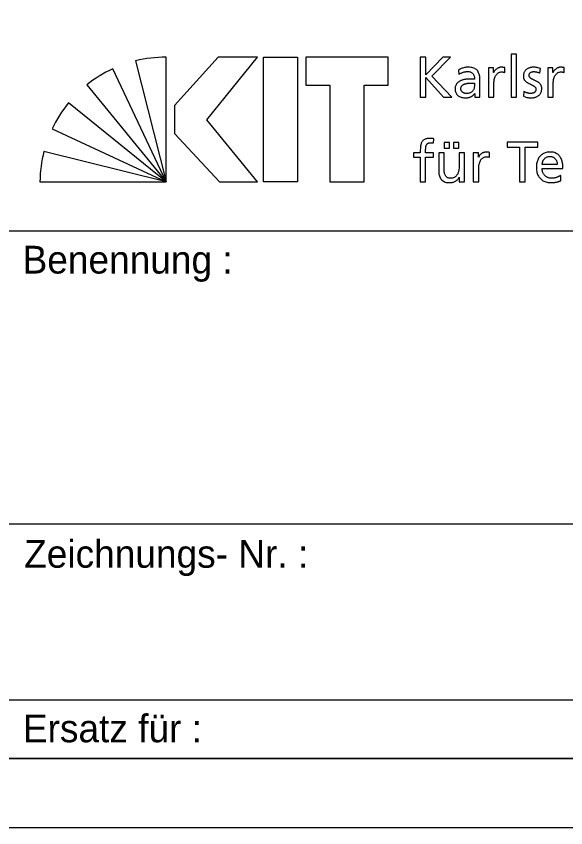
# Model space of a CAD drawing. Extents: x 0 to 75, y 0 to 42.1.
# Drawn here: x 70.583 to 72.566, y 0 to 2.927 of the extents above; entities that cross this region are included whole.
import ezdxf

# ---------------------------------------------------------------- set-up
doc = ezdxf.new("R2010")
doc.units = 0
doc.layers.add('90_Plankopf', color=7, linetype='Continuous')

msp = doc.modelspace()

# ---------------------------------------------------------------- linework, layer by layer
at = {"layer": '90_Plankopf'}
for p, q in [((71.0137, 2.7666), (71.124, 2.3293)), ((71.124, 2.3293), (71.124, 2.7792)), ((72.0405, 2.7793), (72.0405, 2.6353)), ((71.124, 2.3293), (70.9317, 2.7376)), ((72.179, 2.7331), (72.18, 2.7166)), ((72.3463, 2.7242), (72.3463, 2.7416)), ((72.4728, 2.722), (72.4745, 2.7389)), ((72.5606, 2.7242), (72.5606, 2.7416)), ((72.2559, 2.6559), (72.2559, 2.6995)), ((70.8372, 2.6793), (71.124, 2.3293)), ((72.2365, 2.6854), (72.2365, 2.6761)), ((72.0405, 2.6353), (72.0611, 2.6353)), ((72.1253, 2.6353), (72.1554, 2.6353)), ((72.4149, 2.6559), (72.4138, 2.6386)), ((71.124, 2.3293), (70.7717, 2.6143)), ((70.712, 2.5207), (71.124, 2.3293)), ((72.0887, 2.4696), (72.0895, 2.4853)), ((71.124, 2.3293), (70.6829, 2.4394)), ((72.2913, 2.4182), (72.2913, 2.4356)), ((72.5353, 2.392), (72.4808, 2.392)), ((72.4808, 2.3776), (72.5559, 2.3776)), ((72.5479, 2.3337), (72.5479, 2.353)), ((70.6682, 2.3293), (71.124, 2.3293)), ((70.55, 2.1535), (74.75, 2.1535)), ((70.55, 1.096), (74.75, 1.096)), ((70.55, 0.4615), (74.75, 0.4615)), ((74.75, 0.25), (65.856, 0.25)), ((66.44, 0.25), (74.75, 0.25)), ((66.44, 0.25), (74.75, 0.25))]:
    msp.add_line(p, q, dxfattribs=at)
for points in [[(0, 42.05), (75, 42.05), (75, 0), (0, 0)], [(71.4533, 2.7793), (71.3118, 2.7793), (71.1536, 2.6049), (71.1536, 2.5046), (71.3169, 2.3293), (71.4542, 2.3293), (71.2711, 2.5531)], [(71.5985, 2.7793), (71.5985, 2.3293), (71.4751, 2.3293), (71.4751, 2.7793)], [(71.6281, 2.7793), (71.6281, 2.678), (71.7151, 2.678), (71.7151, 2.3293), (71.8385, 2.3293), (71.8385, 2.678), (71.9255, 2.678), (71.9255, 2.7793)]]:
    msp.add_lwpolyline(points, close=True, dxfattribs=at)
for points in [[(59.6038, 0.25), (74.75, 0.25), (74.75, 41.8), (59.6038, 41.8)], [(72.369, 2.6353), (72.3884, 2.6353), (72.3884, 2.79), (72.369, 2.79), (72.369, 2.6353)], [(72.1554, 2.6353), (72.0824, 2.7112), (72.15, 2.7793), (72.1226, 2.7793), (72.0611, 2.716), (72.0611, 2.7793), (72.0405, 2.7793)], [(72.3061, 2.7242), (72.3057, 2.7242), (72.3057, 2.7405), (72.2875, 2.7405), (72.2875, 2.6353), (72.3069, 2.6353), (72.3069, 2.6832)], [(72.5203, 2.7242), (72.5199, 2.7242), (72.5199, 2.7405), (72.5018, 2.7405), (72.5018, 2.6353), (72.5212, 2.6353), (72.5212, 2.6832)], [(72.0611, 2.6353), (72.0611, 2.7059), (72.1253, 2.6353)], [(72.2382, 2.6489), (72.2386, 2.6489), (72.2386, 2.6353), (72.2567, 2.6353)], [(72.1277, 2.4713), (72.1277, 2.4506), (72.1471, 2.4506), (72.1471, 2.4713), (72.1277, 2.4713)], [(72.1615, 2.4713), (72.1615, 2.4506), (72.1809, 2.4506), (72.1809, 2.4713), (72.1615, 2.4713)], [(72.3995, 2.3293), (72.4201, 2.3293), (72.4201, 2.4552), (72.4649, 2.4552), (72.4649, 2.4733), (72.3547, 2.4733), (72.3547, 2.4552), (72.3995, 2.4552), (72.3995, 2.3293)], [(72.0412, 2.4443), (72.0412, 2.4346), (72.0165, 2.4346), (72.0165, 2.4189), (72.0412, 2.4189), (72.0412, 2.3293), (72.0606, 2.3293), (72.0606, 2.4189), (72.0885, 2.4189), (72.0885, 2.4346), (72.0606, 2.4346), (72.0606, 2.4459)], [(72.1271, 2.3801), (72.1271, 2.4346), (72.1077, 2.4346), (72.1077, 2.372)], [(72.2007, 2.3293), (72.2007, 2.4346), (72.1813, 2.4346), (72.1813, 2.3859)], [(72.2511, 2.4182), (72.2507, 2.4182), (72.2507, 2.4346), (72.2325, 2.4346), (72.2325, 2.3293), (72.2519, 2.3293), (72.2519, 2.3772)], [(72.1816, 2.346), (72.182, 2.346), (72.182, 2.3293), (72.2007, 2.3293)]]:
    msp.add_lwpolyline(points, dxfattribs=at)
for centre, start, end in [((71.1224, 2.3028), 89.8053, 103.1895), ((71.1331, 2.3059), 115.0126, 128.3968), ((71.1408, 2.3131), 140.7898, 154.174), ((71.1446, 2.3219), 165.7222, 179.1064)]:
    msp.add_arc(centre, 0.4764, start, end, dxfattribs=at)
for points in [[(72.2559, 2.6995), (72.256, 2.709), (72.2545, 2.717), (72.2517, 2.7235), (72.2488, 2.73), (72.2442, 2.7348), (72.238, 2.7381), (72.2317, 2.7413), (72.2236, 2.743), (72.2136, 2.743), (72.2069, 2.743), (72.2007, 2.742), (72.1949, 2.7402), (72.1891, 2.7384), (72.1838, 2.7361), (72.179, 2.7331)], [(72.18, 2.7166), (72.1826, 2.7188), (72.1856, 2.7207), (72.189, 2.7223), (72.1923, 2.7239), (72.1958, 2.7251), (72.1995, 2.726), (72.2032, 2.7269), (72.2068, 2.7273), (72.2105, 2.7273), (72.217, 2.7273), (72.2221, 2.7263), (72.2259, 2.7243), (72.2297, 2.7222), (72.2324, 2.7191), (72.2341, 2.7151), (72.2358, 2.711), (72.2365, 2.7059), (72.2365, 2.6999)], [(72.3463, 2.7416), (72.345, 2.7418), (72.3437, 2.7421), (72.3425, 2.7423), (72.3412, 2.7425), (72.3399, 2.7427), (72.3385, 2.7428), (72.3371, 2.7429), (72.3354, 2.743), (72.3335, 2.743), (72.3298, 2.743), (72.3261, 2.7422), (72.3226, 2.7406), (72.3191, 2.739), (72.3159, 2.7368), (72.313, 2.7339), (72.3101, 2.7311), (72.3078, 2.7279), (72.3061, 2.7242)], [(72.3069, 2.6832), (72.3069, 2.692), (72.3081, 2.6996), (72.3105, 2.706), (72.3129, 2.7124), (72.3162, 2.7174), (72.3205, 2.7208), (72.3247, 2.7243), (72.3298, 2.726), (72.3356, 2.7261), (72.3373, 2.7261), (72.339, 2.726), (72.3409, 2.7257), (72.3427, 2.7254), (72.3445, 2.7249), (72.3463, 2.7242)], [(72.4745, 2.7389), (72.4707, 2.74), (72.4669, 2.741), (72.463, 2.7418), (72.4591, 2.7426), (72.4549, 2.743), (72.4504, 2.743), (72.4451, 2.743), (72.4403, 2.7423), (72.4358, 2.741), (72.4313, 2.7397), (72.4274, 2.7377), (72.424, 2.735), (72.4206, 2.7323), (72.418, 2.729), (72.4161, 2.7249), (72.4142, 2.7208), (72.4132, 2.7161), (72.4132, 2.7106), (72.4132, 2.7064), (72.4141, 2.7028), (72.4158, 2.6997), (72.4174, 2.6966), (72.4195, 2.694), (72.4223, 2.6917), (72.425, 2.6895), (72.4279, 2.6875), (72.4312, 2.6857), (72.4344, 2.684), (72.4376, 2.6824), (72.4409, 2.6809), (72.4441, 2.6793), (72.4471, 2.6777), (72.4498, 2.6761), (72.4525, 2.6745), (72.4547, 2.6727), (72.4563, 2.6706), (72.4579, 2.6686), (72.4588, 2.6663), (72.4588, 2.6636), (72.4588, 2.6607), (72.4582, 2.6584), (72.457, 2.6564), (72.4558, 2.6545), (72.4542, 2.6529), (72.4522, 2.6518), (72.4503, 2.6506), (72.4482, 2.6498), (72.4459, 2.6493), (72.4435, 2.6487), (72.4412, 2.6485), (72.439, 2.6485), (72.4371, 2.6485), (72.4347, 2.6488), (72.432, 2.6493), (72.4292, 2.6499), (72.4263, 2.6507), (72.4233, 2.6518), (72.4203, 2.6529), (72.4175, 2.6543), (72.4149, 2.6559)], [(72.4138, 2.6386), (72.4183, 2.6363), (72.423, 2.6347), (72.4279, 2.6339), (72.4328, 2.6331), (72.4377, 2.6327), (72.4427, 2.6328), (72.4475, 2.6328), (72.452, 2.6335), (72.4564, 2.6348), (72.4607, 2.6361), (72.4647, 2.6381), (72.4681, 2.6408), (72.4716, 2.6435), (72.4743, 2.6469), (72.4764, 2.651), (72.4784, 2.6551), (72.4794, 2.66), (72.4795, 2.6656), (72.4794, 2.6704), (72.4786, 2.6745), (72.4769, 2.6778), (72.4753, 2.6811), (72.4731, 2.684), (72.4704, 2.6863), (72.4677, 2.6886), (72.4647, 2.6906), (72.4615, 2.6922), (72.4583, 2.6939), (72.455, 2.6954), (72.4518, 2.6968), (72.4486, 2.6983), (72.4456, 2.6998), (72.4429, 2.7013), (72.4402, 2.7029), (72.438, 2.7047), (72.4364, 2.7068), (72.4347, 2.7089), (72.4339, 2.7115), (72.4338, 2.7145), (72.4339, 2.7174), (72.4348, 2.7198), (72.4365, 2.7217), (72.4382, 2.7236), (72.4404, 2.725), (72.4432, 2.7259), (72.446, 2.7269), (72.4491, 2.7273), (72.4524, 2.7273), (72.4536, 2.7273), (72.4551, 2.7271), (72.4569, 2.7269), (72.4588, 2.7266), (72.4607, 2.7261), (72.4627, 2.7256), (72.4648, 2.7251), (72.4667, 2.7246), (72.4685, 2.7239), (72.4703, 2.7233), (72.4717, 2.7226), (72.4728, 2.722)], [(72.5606, 2.7416), (72.5592, 2.7418), (72.5579, 2.7421), (72.5567, 2.7423), (72.5555, 2.7425), (72.5541, 2.7427), (72.5527, 2.7428), (72.5513, 2.7429), (72.5497, 2.743), (72.5478, 2.743), (72.544, 2.743), (72.5404, 2.7422), (72.5368, 2.7406), (72.5333, 2.739), (72.5301, 2.7368), (72.5273, 2.7339), (72.5244, 2.7311), (72.5221, 2.7279), (72.5203, 2.7242)], [(72.5212, 2.6832), (72.5212, 2.692), (72.5224, 2.6996), (72.5247, 2.706), (72.5271, 2.7124), (72.5304, 2.7174), (72.5347, 2.7208), (72.539, 2.7243), (72.544, 2.726), (72.5498, 2.7261), (72.5515, 2.7261), (72.5533, 2.726), (72.5551, 2.7257), (72.557, 2.7254), (72.5588, 2.7249), (72.5606, 2.7242)], [(72.2365, 2.6999), (72.234, 2.7), (72.2317, 2.7001), (72.2295, 2.7001), (72.2273, 2.7002), (72.2251, 2.7003), (72.2229, 2.7003), (72.2208, 2.7003), (72.2184, 2.7003), (72.2159, 2.7003), (72.2118, 2.7003), (72.2076, 2.6999), (72.2031, 2.6992), (72.1987, 2.6985), (72.1943, 2.6973), (72.19, 2.6957), (72.1858, 2.6941), (72.1819, 2.6919), (72.1784, 2.6892), (72.175, 2.6866), (72.1722, 2.6833), (72.1701, 2.6794), (72.1681, 2.6755), (72.1671, 2.6709), (72.167, 2.6656), (72.1671, 2.658), (72.1687, 2.6518), (72.1719, 2.6469), (72.1752, 2.6421), (72.1797, 2.6385), (72.1855, 2.6362), (72.1913, 2.6339), (72.1979, 2.6328), (72.2056, 2.6328), (72.21, 2.6328), (72.214, 2.6334), (72.2175, 2.6344), (72.221, 2.6355), (72.2241, 2.6368), (72.2268, 2.6384), (72.2295, 2.6401), (72.2318, 2.6419), (72.2337, 2.6437), (72.2355, 2.6455), (72.237, 2.6472), (72.2382, 2.6489)], [(72.2365, 2.6761), (72.2365, 2.6709), (72.2354, 2.6661), (72.2332, 2.662), (72.231, 2.6578), (72.2277, 2.6546), (72.2233, 2.6522), (72.219, 2.6498), (72.2136, 2.6485), (72.2072, 2.6485), (72.205, 2.6485), (72.2027, 2.6489), (72.2004, 2.6496), (72.1981, 2.6503), (72.196, 2.6514), (72.1941, 2.6529), (72.1922, 2.6543), (72.1906, 2.6561), (72.1894, 2.6582), (72.1883, 2.6604), (72.1877, 2.6628), (72.1876, 2.6656), (72.1877, 2.6693), (72.1886, 2.6724), (72.1904, 2.6749), (72.1922, 2.6773), (72.1946, 2.6793), (72.1975, 2.6807), (72.2003, 2.6822), (72.2034, 2.6833), (72.2067, 2.6841), (72.21, 2.6848), (72.2132, 2.6853), (72.2163, 2.6855), (72.2194, 2.6858), (72.222, 2.6859), (72.2241, 2.6858), (72.2262, 2.6858), (72.2283, 2.6858), (72.2303, 2.6856), (72.2324, 2.6855), (72.2345, 2.6855), (72.2365, 2.6854)], [(72.2567, 2.6353), (72.2566, 2.6363), (72.2565, 2.6377), (72.2563, 2.6393), (72.2562, 2.6411), (72.2561, 2.6433), (72.2561, 2.646), (72.256, 2.6486), (72.2559, 2.652), (72.2559, 2.6559)], [(72.0895, 2.4853), (72.0875, 2.4856), (72.0855, 2.4859), (72.0834, 2.4862), (72.0812, 2.4864), (72.079, 2.4866), (72.0765, 2.4866), (72.0694, 2.4865), (72.0635, 2.4855), (72.0589, 2.4836), (72.0543, 2.4816), (72.0507, 2.4787), (72.0481, 2.475), (72.0455, 2.4713), (72.0437, 2.4668), (72.0427, 2.4616), (72.0417, 2.4565), (72.0412, 2.4507), (72.0412, 2.4443)], [(72.0606, 2.4459), (72.0606, 2.4495), (72.0608, 2.4528), (72.0612, 2.4558), (72.0616, 2.4588), (72.0625, 2.4615), (72.0637, 2.4637), (72.065, 2.466), (72.0669, 2.4677), (72.0694, 2.469), (72.0719, 2.4702), (72.0752, 2.4709), (72.0794, 2.4709), (72.0811, 2.4709), (72.0828, 2.4708), (72.0844, 2.4706), (72.0861, 2.4703), (72.0875, 2.47), (72.0887, 2.4696)], [(72.2913, 2.4356), (72.29, 2.4359), (72.2887, 2.4361), (72.2875, 2.4363), (72.2863, 2.4365), (72.2849, 2.4367), (72.2835, 2.4368), (72.2821, 2.437), (72.2804, 2.437), (72.2786, 2.437), (72.2748, 2.437), (72.2712, 2.4362), (72.2676, 2.4346), (72.2641, 2.433), (72.2609, 2.4308), (72.2581, 2.428), (72.2552, 2.4252), (72.2529, 2.4219), (72.2511, 2.4182)], [(72.5559, 2.3776), (72.556, 2.3861), (72.5552, 2.394), (72.5536, 2.4012), (72.552, 2.4084), (72.5495, 2.4146), (72.5459, 2.42), (72.5423, 2.4254), (72.5375, 2.4295), (72.5315, 2.4325), (72.5256, 2.4355), (72.5182, 2.437), (72.5095, 2.437), (72.502, 2.437), (72.4953, 2.4357), (72.4892, 2.4331), (72.4832, 2.4305), (72.478, 2.4269), (72.4737, 2.4221), (72.4694, 2.4174), (72.466, 2.4118), (72.4637, 2.4052), (72.4614, 2.3988), (72.4602, 2.3916), (72.4602, 2.3838), (72.4602, 2.3752), (72.4613, 2.3674), (72.4634, 2.3604), (72.4656, 2.3535), (72.469, 2.3475), (72.4734, 2.3425), (72.4779, 2.3375), (72.4835, 2.3336), (72.4904, 2.3309), (72.4973, 2.3282), (72.5053, 2.3269), (72.5147, 2.3268), (72.5204, 2.3269), (72.5253, 2.3273), (72.5293, 2.328), (72.5334, 2.3288), (72.5369, 2.3297), (72.5398, 2.3307), (72.5428, 2.3317), (72.5454, 2.3327), (72.5479, 2.3337)], [(72.2519, 2.3772), (72.252, 2.386), (72.2532, 2.3937), (72.2555, 2.4001), (72.2579, 2.4065), (72.2612, 2.4114), (72.2655, 2.4148), (72.2698, 2.4183), (72.2748, 2.4201), (72.2806, 2.4201), (72.2823, 2.4201), (72.2841, 2.42), (72.2859, 2.4197), (72.2878, 2.4195), (72.2896, 2.419), (72.2913, 2.4182)], [(72.4808, 2.392), (72.4812, 2.3955), (72.482, 2.3989), (72.4832, 2.4024), (72.4844, 2.4058), (72.4861, 2.4089), (72.4884, 2.4118), (72.4906, 2.4147), (72.4934, 2.417), (72.4969, 2.4187), (72.5003, 2.4204), (72.5043, 2.4213), (72.5091, 2.4213), (72.5133, 2.4213), (72.517, 2.4206), (72.5202, 2.419), (72.5235, 2.4175), (72.5262, 2.4154), (72.5285, 2.4127), (72.5307, 2.4101), (72.5324, 2.4069), (72.5335, 2.4034), (72.5347, 2.3999), (72.5353, 2.3961), (72.5353, 2.392)], [(72.1077, 2.372), (72.1077, 2.3626), (72.1091, 2.3545), (72.1118, 2.3478), (72.1146, 2.341), (72.119, 2.3359), (72.1248, 2.3323), (72.1306, 2.3287), (72.138, 2.3269), (72.1471, 2.3268), (72.152, 2.3269), (72.1568, 2.3276), (72.1613, 2.3291), (72.1658, 2.3307), (72.1698, 2.3329), (72.1733, 2.3357), (72.1768, 2.3386), (72.1796, 2.342), (72.1816, 2.346)], [(72.1813, 2.3859), (72.1813, 2.3794), (72.1807, 2.3736), (72.1795, 2.3683), (72.1782, 2.363), (72.1763, 2.3584), (72.1736, 2.3546), (72.171, 2.3507), (72.1677, 2.3478), (72.1637, 2.3457), (72.1596, 2.3436), (72.1549, 2.3426), (72.1494, 2.3425), (72.1438, 2.3429), (72.1393, 2.3444), (72.1361, 2.3473), (72.1328, 2.3501), (72.1305, 2.3542), (72.1291, 2.3597), (72.1277, 2.3651), (72.1271, 2.3719), (72.1271, 2.3801)], [(72.5479, 2.353), (72.5467, 2.3521), (72.5449, 2.351), (72.5426, 2.3497), (72.5403, 2.3485), (72.5377, 2.3474), (72.5347, 2.3463), (72.5317, 2.3452), (72.5286, 2.3443), (72.5253, 2.3436), (72.522, 2.3429), (72.5187, 2.3426), (72.5155, 2.3425), (72.5108, 2.3426), (72.5065, 2.3434), (72.5023, 2.3451), (72.4982, 2.3468), (72.4945, 2.3492), (72.4913, 2.3523), (72.488, 2.3554), (72.4855, 2.359), (72.4836, 2.3633), (72.4818, 2.3676), (72.4809, 2.3724), (72.4808, 2.3776)]]:
    msp.add_open_spline(points, degree=3, dxfattribs=at)

# ---------------------------------------------------------------- texts
for s, p in [('Benennung :', (70.6057, 1.999)), ('Zeichnungs- Nr. :', (70.6114, 0.9379)), ('Ersatz für :', (70.6069, 0.3084))]:
    msp.add_text(s, height=0.1, dxfattribs=at).set_placement(p)

doc.saveas('drawing.dxf')
